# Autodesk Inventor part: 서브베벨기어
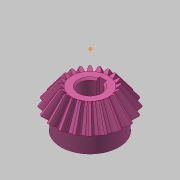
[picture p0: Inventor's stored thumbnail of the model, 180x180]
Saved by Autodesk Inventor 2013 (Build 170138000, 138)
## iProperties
Created: 2018-09
Part Number: 서브베벨기어
Material: 강철, 탄소
Document SubType Name: Modeling
Categories: <?xml version="1.0" encoding="UTF-16"?> <MemberInstance><Categories><FamilyTemplate><FamilyTemplateParameter ValueType="xs:double" Id="1" ObjectReferenceKey="da
Mass: 134.694 g
Surface Area: 63.6444 cm^2
Volume: 17.1585 cm^3
Density: 7.85 g/cm^3
CustomPartVersion: 1
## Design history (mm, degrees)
node "맨 위 점"
node "메쉬 평면2"
sketch "톱니 본체 스케치"
  geometry: L1 (0, 0)-(18.003, -31.331); L2 (18.003, -31.331)-(21.664, -28.891); L3 (21.664, -28.891)-(0, 0); L4 (20, -30)-(0, 0); L5 (10.813, -18.818)-(13.012, -17.352); L6 (18.003, -31.331)-(10.813, -18.818); L7 (21.664, -28.891)-(13.012, -17.352); L8 (0, -39.387)-(0, 6.564) reference; L9 (0, -30)-(21.664, -30)
  constraints: 16 end point, 4 point on line, 3 perpendicular, 2 collinear, 1 horizontal alignment, 1 vertical alignment
  dimensions: "d0" = 40 diameter of L4.start L8 (= da_de); "d1" = 36.00616 diameter of L1.end L8 (= da_dfe); "d2" = 43.3282 diameter of L2.end L8 (= da_dae); "d3" = 14.4 distance between parallel lines of L2 L5 (= da_b); "d4" = 28.8906 vertical distance of L2.end L1.start (= da_ve)
revolve "톱니 본체" sketch "톱니 본체 스케치" stored, may be unused: angle "d5" = 90 deg
node "시작점"
node "톱니 평면"
sketch "시작 스케치"
  geometry: L1 (0, -23.505)-(0, 10.645) reference; L2 (-0.834, -2.928)-(0.834, -2.928); A1 r 8.898 centre (-9.698, -3.713) between (-0.834, -2.928) and (-3.903, 3.04); A2 r 8.898 centre (9.698, -3.713) between (3.903, 3.04) and (0.834, -2.928); A3 r 27.357 centre (0, -24.037) between (3.903, 3.04) and (-3.903, 3.04); 1 further point
  constraints: 6 point on circle, 3 centre point, 3 symmetric about line, 2 end point, 1 coincident, 1 perpendicular, 1 other
  dimensions: "d7" = 8.89846 radius of A1 (= fd_rr); "d8" = 9.69794 horizontal distance of point (0, -24.037) A1.centre (= fd_x); "d9" = 20.32439 vertical distance of point (0, -24.037) A1.centre (= fd_y); "d57" = 27.35701 radius of A3 (= 0.5 x fd_dva + 0.3 x da_he); "d58" = 21.10901 distance from line of A3.centre L2 (= 0.5 x fd_dva - 1.12 x da_he)
node "끝점"
  node "끝 평면"
sketch "3D 스케치 오른쪽"
  node "Helical Curve Right" dims "d65" = 229.90621 (computed from da_dm, da_delta, da_beta), "d66" = 31.5, "d67" = 40 (= da_de), "d68" = -5.88003 (= -da_delta), "d69" = 12.16458 (computed from fd_loft, da_delta)
node "끝 평면 오른쪽"
sketch "끝 스케치 오른쪽"
  geometry: L1 (0, -22.649)-(0, 12.15) reference; L2 (-0.497, -1.72)-(0.497, -1.72); A1 r 5.299 centre (-5.775, -2.187) between (-0.497, -1.72) and (-2.324, 1.834); A2 r 5.299 centre (5.775, -2.187) between (2.324, 1.834) and (0.497, -1.72); A3 r 16.291 centre (0, -14.29) between (2.324, 1.834) and (-2.324, 1.834); 1 further point
  constraints: 6 point on circle, 3 centre point, 3 symmetric about line, 2 end point, 1 coincident, 1 perpendicular, 1 other
  dimensions: "d70" = 5.77526 horizontal distance of A3.centre A1.centre (computed from fd_x, fd_ratio); "d71" = 12.10346 vertical distance of point (0, -14.29) A1.centre (computed from fd_y, fd_ratio); "d72" = 5.29916 radius of A1 (computed from fd_rr, fd_ratio); "d73" = 12.57071 distance from line of point (0, -14.29) L2 (computed from d58, fd_ratio); "d74" = 16.29149 radius of A3 (computed from d57, fd_ratio)
feature "로프트 오른쪽" sketch "끝 스케치 오른쪽" dims "d75" = 0, "d77" = 0, "d79" = 0, "d80" = 90 deg, "d85" = 20, "d92" = 90 deg, "d93" = 90 deg, "da_teethtype" = 0 [user parameter]
sketch "3D 스케치 왼쪽"
  node "Helical Curve Left" dims "d26" = 229.90621 (computed from da_dm, da_delta, da_beta), "d27" = 12.16458 (computed from fd_loft, da_delta), "d28" = 40 (= da_de), "d29" = -5.88003 (= -da_delta)
node "끝 평면 왼쪽"
sketch "끝 스케치 왼쪽" dims "d56" = 10.82768 (derived)
  geometry: L1 (0, -35.087)-(0, 18.089) reference; L2 (-0.497, -1.716)-(0.497, -1.716); A1 r 5.299 centre (-5.775, -2.183) between (-0.497, -1.716) and (-2.324, 1.838); A2 r 5.299 centre (5.775, -2.183) between (2.324, 1.838) and (0.497, -1.716); A3 r 16.291 centre (0, -14.287) between (2.324, 1.838) and (-2.324, 1.838); 2 further points; 1 other entity
  constraints: 6 point on circle, 3 centre point, 3 symmetric about line, 2 end point, 1 coincident, 2 other
  dimensions: "d30" = 5.29916 radius of A1 (computed from fd_rr, fd_ratio); "d31" = 5.77526 horizontal distance of point (0, -14.287) A1.centre (computed from fd_x, fd_ratio); "d32" = 12.10346 vertical distance of A1.centre point (0, -14.287) (computed from fd_y, fd_ratio); "d61" = 16.29149 radius of A3 (computed from d57, fd_ratio); "d62" = 12.57071 distance from line of point (0, -14.287) L2 (computed from d58, fd_ratio)
feature "로프트 왼쪽" sketch "끝 스케치 왼쪽" dims "d35" = 0, "d37" = 0, "d39" = 0, "d40" = 90 deg, "d84" = 10, "d90" = 90 deg, "d91" = 90 deg, "da_teethtype" = 0 [user parameter]
sketch "본체 스케치"
  geometry: L1 (0, -35.038)-(0, -19.531) reference; L2 (18.003, -31.331)-(10.813, -18.818) reference; L3 (10.813, -18.818)-(0, -18.818); L4 (18.003, -31.331)-(0, -31.331)
  constraints: 4 end point, 2 perpendicular, 2 point on line
revolve "본체 고정" sketch "본체 스케치" stored, may be unused: angle "d46" = 90 deg
feature "피치 지름" dims angle "d47" = 90 deg
sketch "스케치8"
  geometry: C1 r 17 at (0, 0); 1 further point
  constraints: 1 centre point, 1 coincident
  dimensions: "d94" = 34 diameter of C1
extrude "돌출1" join sketch "스케치8" distance "d95" = 10; taper "d96" = 0 deg
sketch "스케치9"
  geometry: 1 further point
hole "구멍1" sketch "스케치9" at (0, 0) diameter "d97" = 12; stored, may be unused: countersink angle "d101" = 90 deg, drill point angle "d103" = 118 deg; dims "d98" = 6, "d99" = 4, "d100" = 2, "d102" = 8
sketch "스케치10"
  geometry: 1 further point
sketch "스케치11"
  geometry: 1 further point
sketch "스케치12"
  geometry: L1 (-2, 5.657)-(-2, 7.8); L2 (-2, 7.8)-(2, 7.8); L3 (2, 7.8)-(2, 5.657); A1 r 6 centre (0, 0) between (-2, 5.657) and (2, 5.657) reference; 1 further point
  constraints: 6 end point, 2 parallel, 2 point on circle, 1 perpendicular, 1 vertical
  dimensions: "d104" = 4 distance of L1.end L2.end; "d105" = 13.8 dimension on A1 L2
extrude "돌출2" cut sketch "스케치12" stored distance "d106" = 7; taper "d107" = 0 deg
chamfer "모따기1" distance "d108" = 1; stored, may be unused: second distance "d109" = 2, angle "d110" = 45 deg
body "Solid1"
feature "로프트" dims "d17" = 0, "d18" = 90 deg, "d19" = 0, "d20" = 90 deg, "d89" = 0, "da_teethtype" = 0 [user parameter]
pattern_circular "원형 패턴" dims angle "d22" = 360 deg, "d88" = 0, "da_teethtype" = 0 [user parameter]
pattern_circular "원형 패턴 오른쪽" dims angle "d82" = 360 deg, "da_teethtype" = 0 [user parameter]
pattern_circular "원형 패턴 왼쪽" dims angle "d42" = 360 deg, "da_teethtype" = 0 [user parameter]
sketch "끝 스케치"
  geometry: L1 (0, -15.359)-(0, 6.983) reference; L2 (-0.497, -1.72)-(0.497, -1.72); A1 r 5.299 centre (-5.775, -2.187) between (-0.497, -1.72) and (-2.324, 1.834); A2 r 5.299 centre (5.775, -2.187) between (2.324, 1.834) and (0.497, -1.72); A3 r 16.291 centre (0, -14.29) between (2.324, 1.834) and (-2.324, 1.834); 1 further point
  constraints: 6 point on circle, 3 centre point, 3 symmetric about line, 2 end point, 1 coincident, 1 other
  dimensions: "d12" = 5.29916 radius of A1 (computed from fd_rr, fd_ratio); "d15" = 5.77526 horizontal distance of A1.centre point (0, -14.29) (computed from fd_x, fd_ratio); "d16" = 12.10346 vertical distance of A1.centre point (0, -14.29) (computed from fd_y, fd_ratio); "d59" = 16.29149 radius of A3 (computed from d57, fd_ratio); "d60" = 12.57071 distance from line of A3.centre L2 (computed from d58, fd_ratio)
sketch "Sketch6"
  geometry: L1 (20, -30)-(0, 0) reference; L2 (0, -37.8)-(0, 6.3) reference
body "Srf1"
other parameters: "da_b" = 14.4 [user parameter; used in 2 equation terms], "da_de" = 40 [user parameter; used in 4 equation terms], "da_dae" = 43.3282 [user parameter; used in 2 equation terms], "da_dfe" = 36.00616 [user parameter; used in 1 equation term], "da_le" = 36.05551 [user parameter; used in 1 equation term], "da_omega" = 90 deg [user parameter; used in 1 equation term], "da_beta" = 0 [user parameter; used in 2 equation terms], "da_delta" = 5.88003 [user parameter; used in 8 equation terms], "da_alpha" = 20 deg [user parameter; used in 2 equation terms], "da_he" = 4.4 [user parameter; used in 4 equation terms], "da_ve" = 28.8906 [user parameter; used in 1 equation term], "fd_dv" = 48.07402 (computed from da_de, da_delta) [user parameter; used in 1 equation term], "fd_dva" = 52.07402 (computed from da_dae, da_delta) [user parameter; used in 3 equation terms], "fd_dvb" = 45.1748 (computed from fd_dv, da_alpha) [user parameter; used in 2 equation terms], "da_zv" = 240.37008 [user parameter; used in 1 equation term], "fd_loft" = 14.62 (= da_b + 0.05 x da_he) [user parameter; used in 4 equation terms], "fd_ratio" = 5.95514 (computed from da_le, fd_loft) [user parameter; used in 15 equation terms], "fd_rr" = 8.89846 (computed from fd_dd, fd_dvb) [user parameter; used in 6 equation terms], "fd_angle" = 0.66075 (computed from da_zv) [user parameter; used in 4 equation terms], "fd_x1" = 1.58709 (computed from da_dvw, fd_angle) [user parameter; used in 1 equation term], "fd_y1" = 23.98456 (computed from da_dvw, fd_angle) [user parameter; used in 1 equation term], "fd_x2" = 8.11084 (computed from fd_rr, fd_angle2, fd_angle) [user parameter; used in 1 equation term], "fd_y2" = 3.66016 (computed from fd_rr, fd_angle2, fd_angle) [user parameter; used in 1 equation term], "fd_x" = 9.69794 (= fd_x1 + fd_x2) [user parameter; used in 4 equation terms], "fd_y" = 20.32439 (= fd_y1 - fd_y2) [user parameter; used in 4 equation terms], "fd_angle2" = 3.57832 (computed from fd_dvb, fd_dd, da_alpha) [user parameter; used in 2 equation terms], "fd_dd" = 48.55402 (= fd_dva - 0.8 x da_he) [user parameter; used in 2 equation terms], "da_dvw" = 48.07402 [user parameter; used in 2 equation terms], "d11" = 14.62 (= fd_loft), "da_dm" = 32.01232 [user parameter; used in 2 equation terms], "da_x" = 0 [user parameter], "da_m" = 2 [user parameter], "d48" = 0, "d49" = 0, "d50" = 90 deg (= da_omega), "d51" = 9 deg (computed from da_z), "d52" = 0, "d53" = 0, "d54" = 0
